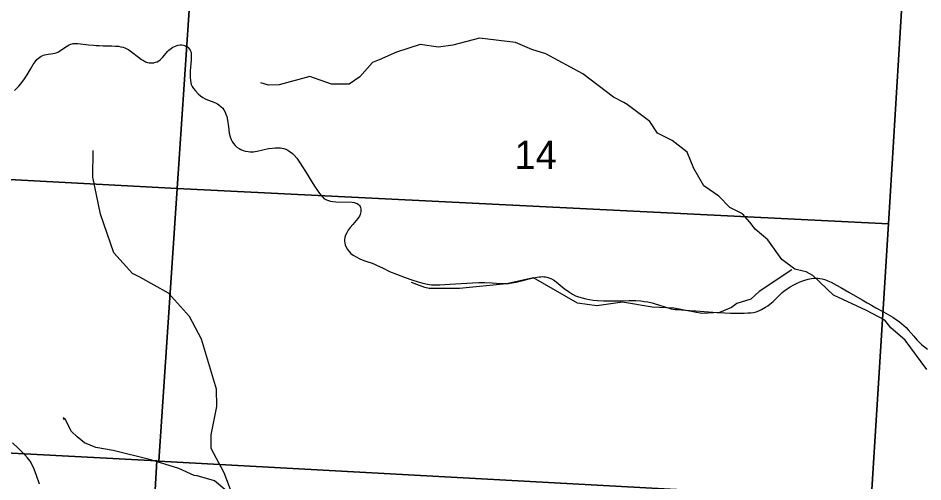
# Model space of a CAD drawing. Extents: x 396.2 to 468.4, y 232.6 to 279.1.
# Drawn here: x 418.195 to 419.533, y 271.358 to 272.044 of the extents above; entities that cross this region are included whole.
import ezdxf

# ---------------------------------------------------------------- set-up
doc = ezdxf.new("R2010")
doc.units = 0
for name, color, linetype in [('GM_X_County_Road', 7, 'Continuous'), ('GM_X_Minor_River', 7, 'Continuous'), ('GM_X_Section', 7, 'Continuous'), ('GM_X_Section_Text', 7, 'Continuous')]:
    doc.layers.add(name, color=color, linetype=linetype)

msp = doc.modelspace()

# ---------------------------------------------------------------- linework, layer by layer
at = {"layer": 'GM_X_County_Road'}
for points in [[(418.1898, 271.9369), (418.1962, 271.9435), (418.2006, 271.9486), (418.2048, 271.954), (418.2089, 271.9602), (418.2135, 271.9684), (418.2176, 271.9753), (418.2205, 271.9794), (418.2232, 271.9827), (418.2252, 271.9846), (418.2274, 271.9863), (418.2295, 271.9876), (418.2319, 271.9888), (418.2344, 271.9898), (418.2372, 271.9903), (418.2396, 271.9907), (418.2439, 271.9912), (418.2467, 271.9915), (418.2494, 271.9921), (418.2518, 271.9928), (418.254, 271.9938), (418.2556, 271.9947), (418.2593, 271.9969), (418.266, 272.0014), (418.2709, 272.0042), (418.2735, 272.0052), (418.275, 272.0057), (418.2766, 272.0062), (418.2779, 272.0064), (418.2795, 272.0065), (418.2812, 272.0065), (418.2835, 272.0064), (418.2993, 272.0044), (418.3066, 272.0037), (418.3109, 272.0034), (418.3152, 272.0032), (418.3209, 272.003), (418.3337, 272.0028), (418.3391, 272.0026), (418.3437, 272.0022), (418.3472, 272.0016), (418.3505, 272.0008), (418.3533, 271.9998), (418.356, 271.9986), (418.3589, 271.9969), (418.363, 271.9941), (418.3733, 271.9861), (418.3779, 271.9829), (418.3808, 271.981), (418.3838, 271.9793), (418.3866, 271.9784), (418.3892, 271.9779), (418.3916, 271.9776), (418.3938, 271.9776), (418.3961, 271.9779), (418.3986, 271.9786), (418.4011, 271.9795), (418.4034, 271.9807), (418.4054, 271.9824), (418.409, 271.9858), (418.4168, 271.9948), (418.4184, 271.9964), (418.4204, 271.9982), (418.4222, 271.9996), (418.4242, 272.001), (418.4265, 272.0021), (418.429, 272.003), (418.432, 272.0038), (418.4351, 272.0042), (418.4376, 272.0042), (418.4401, 272.0038), (418.442, 272.0033), (418.4435, 272.0026), (418.4451, 272.0018), (418.4467, 272.0005), (418.4483, 271.9987), (418.4497, 271.9966), (418.4507, 271.9944), (418.4511, 271.9923), (418.4514, 271.9901), (418.4514, 271.9879), (418.4511, 271.982), (418.4503, 271.9715), (418.4499, 271.9653), (418.4496, 271.9604), (418.4497, 271.956), (418.4501, 271.9517), (418.4507, 271.948), (418.4514, 271.9456), (418.4527, 271.9428), (418.4548, 271.9397), (418.4575, 271.9364), (418.4618, 271.9319), (418.4651, 271.929), (418.4687, 271.9265), (418.4719, 271.9247), (418.4753, 271.9231), (418.4823, 271.9205), (418.488, 271.9181), (418.4901, 271.917), (418.4923, 271.9156), (418.4957, 271.9129), (418.4979, 271.9106), (418.4996, 271.9081), (418.5015, 271.9049), (418.5027, 271.9021), (418.5039, 271.8985), (418.5051, 271.8931), (418.5063, 271.8832), (418.5076, 271.8739), (418.5088, 271.8685), (418.5103, 271.8644), (418.5117, 271.8617), (418.5138, 271.8586), (418.5162, 271.8557), (418.5189, 271.8532), (418.522, 271.851), (418.5247, 271.8495), (418.5281, 271.8481), (418.5317, 271.8471), (418.5354, 271.8465), (418.5384, 271.8462), (418.5408, 271.8461), (418.5435, 271.8462), (418.546, 271.8466), (418.5487, 271.8471), (418.5571, 271.8491), (418.5656, 271.851), (418.5717, 271.8519), (418.5757, 271.8523), (418.5796, 271.8524), (418.5832, 271.8521), (418.5858, 271.8517), (418.5884, 271.8511), (418.5913, 271.85), (418.594, 271.8487), (418.5977, 271.8464), (418.601, 271.8437), (418.6036, 271.8411), (418.6073, 271.8367), (418.6115, 271.8312), (418.6161, 271.8243), (418.6203, 271.8174), (418.6241, 271.811), (418.6287, 271.8036), (418.6347, 271.7942), (418.6381, 271.789), (418.6412, 271.7845), (418.6439, 271.7811), (418.6458, 271.779), (418.6475, 271.7775), (418.6494, 271.7763), (418.6515, 271.7752), (418.6543, 271.7741), (418.6571, 271.7733), (418.6609, 271.7727), (418.665, 271.7724), (418.6891, 271.7717), (418.6922, 271.7713), (418.6937, 271.771), (418.6952, 271.7705), (418.6968, 271.7698), (418.6988, 271.7684), (418.7001, 271.7671), (418.701, 271.7655), (418.7017, 271.7639), (418.7022, 271.7621), (418.7024, 271.7606), (418.7024, 271.7591), (418.7023, 271.7576), (418.7019, 271.7556), (418.7011, 271.7534), (418.7, 271.7512), (418.6975, 271.7476), (418.6901, 271.7386), (418.6865, 271.7343), (418.6836, 271.7303), (418.6813, 271.7267), (418.6797, 271.7233), (418.6786, 271.7198), (418.6782, 271.7169), (418.6781, 271.7142), (418.6785, 271.7112), (418.6791, 271.7088), (418.6805, 271.7053), (418.6824, 271.7021), (418.6846, 271.6992), (418.6876, 271.696), (418.6908, 271.6937), (418.6953, 271.6909), (418.7009, 271.6881), (418.7064, 271.6858), (418.7126, 271.6837), (418.7175, 271.6821), (418.7214, 271.6807), (418.7253, 271.6789), (418.7297, 271.6769), (418.7352, 271.6743), (418.7448, 271.6696), (418.7549, 271.6653), (418.7677, 271.6604), (418.7778, 271.657), (418.7871, 271.6541), (418.794, 271.6522), (418.8006, 271.6507), (418.8036, 271.6502), (418.8067, 271.6499), (418.8123, 271.6495), (418.8191, 271.6495), (418.8339, 271.6505), (418.8674, 271.6526), (418.8767, 271.6531), (418.8854, 271.6531), (418.8965, 271.6525), (418.9089, 271.6517), (418.9157, 271.6515), (418.9182, 271.6516), (418.9207, 271.6517), (418.9256, 271.6524), (418.9317, 271.6536), (418.9417, 271.6561), (418.9512, 271.6587), (418.9574, 271.6601), (418.963, 271.6611), (418.966, 271.6615), (418.9686, 271.6617), (418.9707, 271.6618), (418.9729, 271.6617), (418.9751, 271.6614), (418.9772, 271.661), (418.9802, 271.6601), (418.9831, 271.659), (418.9869, 271.6569), (418.991, 271.6541), (419.0031, 271.6444), (419.0106, 271.6388), (419.0153, 271.6358), (419.0197, 271.6336), (419.0243, 271.6318), (419.0296, 271.6302), (419.0348, 271.629), (419.0403, 271.6279), (419.0458, 271.627), (419.0523, 271.6263), (419.061, 271.6258), (419.0728, 271.6258), (419.087, 271.6262), (419.0988, 271.6265), (419.1088, 271.6263), (419.1162, 271.6258), (419.1211, 271.6252), (419.1266, 271.6243), (419.1332, 271.6229), (419.1373, 271.6217), (419.1426, 271.6201), (419.1519, 271.6169), (419.1584, 271.615), (419.1609, 271.6144), (419.1639, 271.6139), (419.1669, 271.6134), (419.1703, 271.6131), (419.1885, 271.6117), (419.1974, 271.6111), (419.2098, 271.6103), (419.2292, 271.6088), (419.2406, 271.6082), (419.2488, 271.6078), (419.2574, 271.6078), (419.269, 271.608), (419.2745, 271.6082), (419.2791, 271.6084), (419.2828, 271.6089), (419.2867, 271.6099), (419.2906, 271.6113), (419.2948, 271.6131), (419.3007, 271.6165), (419.304, 271.6185), (419.3073, 271.6209), (419.3097, 271.6229), (419.312, 271.625), (419.3229, 271.636), (419.3252, 271.6382), (419.3276, 271.6401), (419.3326, 271.6437), (419.3373, 271.6466), (419.3427, 271.6497), (419.3493, 271.653), (419.3545, 271.6552), (419.3586, 271.6566), (419.3639, 271.658), (419.3687, 271.6589), (419.3723, 271.6593), (419.3752, 271.6595), (419.378, 271.6594), (419.3809, 271.6591), (419.3843, 271.6586), (419.3884, 271.6575), (419.393, 271.6558), (419.3976, 271.6538), (419.4058, 271.6494), (419.4123, 271.6457), (419.424, 271.6388), (419.4434, 271.6275), (419.4509, 271.6232), (419.4574, 271.6196), (419.4639, 271.6159), (419.4753, 271.6096), (419.4823, 271.6056), (419.4888, 271.6018), (419.4945, 271.5981), (419.4985, 271.5953), (419.5018, 271.5927), (419.5054, 271.5897), (419.5085, 271.5866), (419.5117, 271.583), (419.5198, 271.5737), (419.5244, 271.5685), (419.5278, 271.5651), (419.5315, 271.5616), (419.5401, 271.5544)], [(418.2269, 271.355), (418.2224, 271.3679), (418.2189, 271.3773), (418.2161, 271.3835), (418.2129, 271.3888), (418.2111, 271.3915), (418.2093, 271.3938), (418.2052, 271.3985), (418.1959, 271.4077), (418.1868, 271.4161)]]:
    msp.add_lwpolyline(points, dxfattribs=at)
at = {"layer": 'GM_X_Minor_River'}
for points in [[(419.5395, 271.5243), (419.5071, 271.5679), (419.4858, 271.5861), (419.477, 271.5973), (419.4499, 271.6115), (419.4014, 271.6343), (419.3705, 271.6634), (419.3609, 271.669), (419.3564, 271.6699), (419.344, 271.673), (419.3248, 271.6869), (419.3041, 271.716), (419.2853, 271.7318), (419.2773, 271.7423), (419.2667, 271.7545), (419.2481, 271.7642), (419.2316, 271.7806), (419.2097, 271.7958), (419.1946, 271.8217), (419.1848, 271.8456), (419.1626, 271.863), (419.141, 271.8739), (419.1294, 271.891), (419.0962, 271.916), (419.091, 271.9192), (419.0761, 271.9269), (419.0303, 271.9614), (418.9756, 271.9909), (418.955, 271.9976), (418.9311, 272.0078), (418.8776, 272.0141), (418.8384, 272.004), (418.8168, 272.0009), (418.7901, 272.0047), (418.7549, 271.9937), (418.7293, 271.982), (418.7193, 271.9785), (418.7009, 271.9571), (418.6847, 271.9462), (418.6586, 271.9463), (418.6268, 271.9575), (418.5815, 271.9453), (418.5656, 271.945), (418.5544, 271.9484)], [(418.5135, 271.3367), (418.4999, 271.372), (418.4807, 271.4076), (418.481, 271.4278), (418.4894, 271.47), (418.4885, 271.4954), (418.4664, 271.5693), (418.4488, 271.6027), (418.4178, 271.6371), (418.3752, 271.6612), (418.3645, 271.6664), (418.337, 271.697), (418.3173, 271.7543), (418.3056, 271.8089), (418.3061, 271.8484)], [(419.3398, 271.6716), (419.2912, 271.6397), (419.2791, 271.6287), (419.2585, 271.6222), (419.2504, 271.6163), (419.2324, 271.6089), (419.2067, 271.6071), (419.165, 271.6153), (419.1329, 271.6167), (419.0892, 271.6238), (419.0513, 271.6185), (419.0227, 271.6225), (418.9577, 271.6602), (418.9177, 271.6513), (418.8483, 271.6444), (418.803, 271.6443), (418.7966, 271.6456), (418.7772, 271.6531)], [(418.4855, 271.36), (418.4601, 271.3674), (418.4556, 271.3678), (418.4329, 271.3784), (418.3916, 271.3912), (418.3357, 271.4048), (418.3104, 271.4093), (418.2933, 271.4161), (418.2827, 271.4252), (418.274, 271.4331), (418.2649, 271.4513), (418.2619, 271.4529), (418.2627, 271.4506)], [(418.574, 271.2863), (418.4855, 271.36)]]:
    msp.add_lwpolyline(points, dxfattribs=at)
at = {"layer": 'GM_X_Section'}
for points in [[(419.5162, 272.3211), (420.0191, 272.3027), (420.5671, 272.2854), (420.4987, 271.28), (419.4571, 271.3312), (419.4827, 271.7399), (419.5072, 272.1445)], [(418.4583, 272.2026), (418.4305, 271.792), (417.3807, 271.8484), (417.3984, 272.258)], [(419.5072, 272.1445), (419.4827, 271.7399), (418.4305, 271.792), (418.4583, 272.2026)], [(417.3807, 271.8484), (418.4305, 271.792), (418.4032, 271.3891), (418.4006, 271.3893), (417.365, 271.4443)], [(418.4305, 271.792), (419.4827, 271.7399), (419.4571, 271.3312), (418.4032, 271.3891)], [(417.365, 271.4443), (418.4006, 271.3893), (418.3421, 270.3767), (417.3152, 270.4295)], [(418.4006, 271.3893), (418.4032, 271.3891), (419.4571, 271.3312), (419.3993, 270.3259), (418.3421, 270.3767)]]:
    msp.add_lwpolyline(points, close=True, dxfattribs=at)

# ---------------------------------------------------------------- texts
at = {"layer": 'GM_X_Section_Text'}
msp.add_text('14', height=0.04186, rotation=0, dxfattribs=at).set_placement((418.9296, 271.821))

doc.saveas('drawing.dxf')
